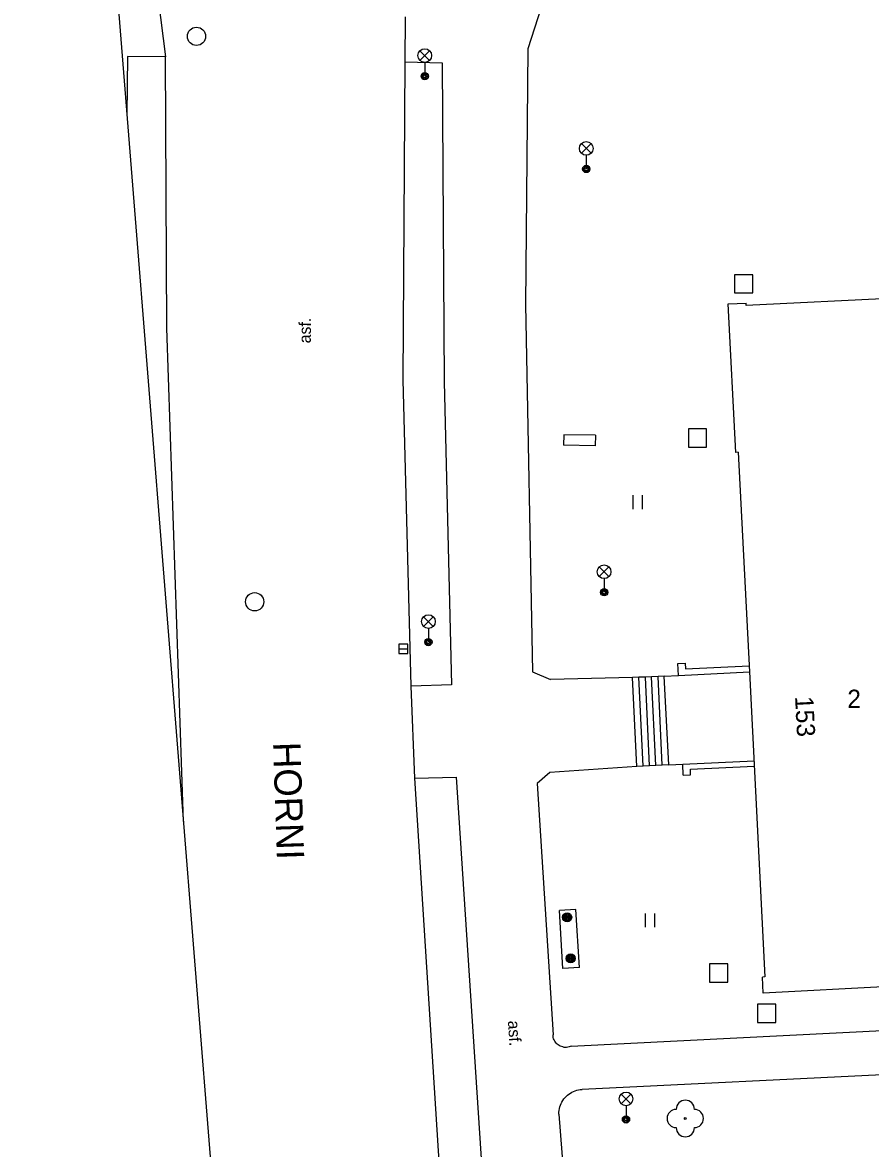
# Model space of a CAD drawing. Extents: x -641829 to -641525, y -1114855 to -1114359.
# Drawn here: x -641828.7 to -641782.2, y -1114487.2 to -1114425.4 of the extents above; entities that cross this region are included whole.
import ezdxf

# ---------------------------------------------------------------- set-up
doc = ezdxf.new("R2010")
doc.units = 0
for name, color, linetype in [('Vrstva 1', 7, 'Continuous'), ('Vrstva 10', 7, 'Continuous'), ('Vrstva 11', 7, 'Continuous'), ('Vrstva 22', 7, 'Continuous'), ('Vrstva 25', 7, 'Continuous'), ('Vrstva 26', 7, 'Continuous'), ('Vrstva 27', 7, 'Continuous'), ('Vrstva 33', 7, 'Continuous'), ('Vrstva 36', 7, 'Continuous'), ('Vrstva 40', 7, 'Continuous'), ('Vrstva 46', 7, 'Continuous'), ('Vrstva 47', 7, 'Continuous'), ('Vrstva 49', 7, 'Continuous'), ('Vrstva 5', 7, 'Continuous')]:
    doc.layers.add(name, color=color, linetype=linetype)

msp = doc.modelspace()

# ---------------------------------------------------------------- linework, layer by layer
at = {"layer": 'Vrstva 1'}
msp.add_line((-641828.67, -1114358.89), (-641812.64, -1114559.36), dxfattribs=at)
at = {"layer": 'Vrstva 10'}
for p, q in [((-641821.23, -1114424.14), (-641820.82, -1114427.32)), ((-641807.68, -1114427.59), (-641807.67, -1114425.11)), ((-641820.76, -1114442.18), (-641820.82, -1114427.32)), ((-641807.8, -1114445.03), (-641807.68, -1114427.59)), ((-641819.847, -1114469.232), (-641820.76, -1114442.18)), ((-641807.36, -1114461.82), (-641807.8, -1114445.03)), ((-641807.15, -1114466.87), (-641807.36, -1114461.82)), ((-641805.78, -1114488.44), (-641807.15, -1114466.87))]:
    msp.add_line(p, q, dxfattribs=at)
at = {"layer": 'Vrstva 11'}
for p, q in [((-641800.22, -1114424.61), (-641800.95, -1114426.88)), ((-641800.95, -1114426.88), (-641801.09, -1114440.89)), ((-641822.92, -1114427.3), (-641822.945, -1114430.492)), ((-641820.82, -1114427.32), (-641822.92, -1114427.3)), ((-641807.68, -1114427.59), (-641805.66, -1114427.64)), ((-641805.66, -1114427.64), (-641805.54, -1114445.13)), ((-641801.09, -1114440.89), (-641800.69, -1114461.04)), ((-641805.54, -1114445.13), (-641805.15, -1114461.75)), ((-641798.98, -1114448.03), (-641798.99, -1114448.61)), ((-641797.25, -1114448.06), (-641798.98, -1114448.03)), ((-641797.25, -1114448.06), (-641797.26, -1114448.64)), ((-641797.26, -1114448.64), (-641798.99, -1114448.61)), ((-641792.72, -1114460.58), (-641792.32, -1114460.56)), ((-641792.69, -1114461.23), (-641792.72, -1114460.58)), ((-641792.32, -1114460.56), (-641792.3, -1114460.86)), ((-641800.69, -1114461.04), (-641799.72, -1114461.46)), ((-641792.69, -1114461.23), (-641788.8, -1114461.04)), ((-641792.3, -1114460.86), (-641788.82, -1114460.7)), ((-641805.15, -1114461.75), (-641807.36, -1114461.82)), ((-641795.21, -1114461.35), (-641799.72, -1114461.46)), ((-641794.86, -1114461.33), (-641795.21, -1114461.35)), ((-641794.98, -1114466.22), (-641795.21, -1114461.35)), ((-641794.51, -1114461.32), (-641794.86, -1114461.33)), ((-641794.63, -1114466.2), (-641794.86, -1114461.33)), ((-641794.17, -1114461.3), (-641794.51, -1114461.32)), ((-641794.28, -1114466.18), (-641794.51, -1114461.32)), ((-641793.81, -1114461.28), (-641794.17, -1114461.3)), ((-641793.93, -1114466.16), (-641794.17, -1114461.3)), ((-641793.47, -1114461.27), (-641793.81, -1114461.28)), ((-641793.58, -1114466.15), (-641793.81, -1114461.28)), ((-641793.47, -1114461.27), (-641792.69, -1114461.23)), ((-641793.23, -1114466.13), (-641793.47, -1114461.27)), ((-641793.23, -1114466.13), (-641793.58, -1114466.15)), ((-641793.23, -1114466.13), (-641792.45, -1114466.09)), ((-641792.45, -1114466.09), (-641788.55, -1114465.91)), ((-641792.43, -1114466.69), (-641792.45, -1114466.09)), ((-641799.74, -1114466.55), (-641800.44, -1114467.16)), ((-641794.98, -1114466.22), (-641799.74, -1114466.55)), ((-641794.63, -1114466.2), (-641794.98, -1114466.22)), ((-641794.28, -1114466.18), (-641794.63, -1114466.2)), ((-641793.93, -1114466.16), (-641794.28, -1114466.18)), ((-641793.58, -1114466.15), (-641793.93, -1114466.16)), ((-641792.43, -1114466.69), (-641792.03, -1114466.67)), ((-641792.04, -1114466.37), (-641788.54, -1114466.2)), ((-641792.03, -1114466.67), (-641792.04, -1114466.37)), ((-641807.15, -1114466.87), (-641804.88, -1114466.8)), ((-641804.88, -1114466.8), (-641803.1, -1114493.92)), ((-641800.44, -1114467.16), (-641799.57, -1114480.94)), ((-641798.32, -1114474.07), (-641799.22, -1114474.12)), ((-641799.03, -1114477.29), (-641799.22, -1114474.12)), ((-641798.13, -1114477.24), (-641798.32, -1114474.07)), ((-641798.13, -1114477.24), (-641799.03, -1114477.29)), ((-641798.58, -1114481.55), (-641766.27, -1114479.92)), ((-641799.57, -1114481.01), (-641799.57, -1114480.94)), ((-641799.56, -1114481.08), (-641799.57, -1114481.01)), ((-641799.54, -1114481.15), (-641799.56, -1114481.08)), ((-641799.51, -1114481.21), (-641799.54, -1114481.15)), ((-641799.48, -1114481.28), (-641799.51, -1114481.21)), ((-641799.44, -1114481.34), (-641799.48, -1114481.28)), ((-641799.4, -1114481.39), (-641799.44, -1114481.34)), ((-641799.35, -1114481.44), (-641799.4, -1114481.39)), ((-641799.3, -1114481.49), (-641799.35, -1114481.44)), ((-641799.24, -1114481.52), (-641799.3, -1114481.49)), ((-641799.18, -1114481.56), (-641799.24, -1114481.52)), ((-641799.11, -1114481.58), (-641799.18, -1114481.56)), ((-641799.04, -1114481.6), (-641799.11, -1114481.58)), ((-641798.63, -1114481.57), (-641798.69, -1114481.59)), ((-641798.58, -1114481.55), (-641798.63, -1114481.57)), ((-641798.97, -1114481.62), (-641799.04, -1114481.6)), ((-641798.9, -1114481.62), (-641798.97, -1114481.62)), ((-641798.83, -1114481.62), (-641798.9, -1114481.62)), ((-641798.76, -1114481.61), (-641798.83, -1114481.62)), ((-641798.69, -1114481.59), (-641798.76, -1114481.61)), ((-641758.49, -1114482), (-641797.98, -1114483.93)), ((-641798.54, -1114484.08), (-641798.45, -1114484.04)), ((-641798.45, -1114484.04), (-641798.36, -1114484)), ((-641798.36, -1114484), (-641798.27, -1114483.97)), ((-641798.27, -1114483.97), (-641798.17, -1114483.95)), ((-641798.17, -1114483.95), (-641798.08, -1114483.94)), ((-641798.08, -1114483.94), (-641797.98, -1114483.93)), ((-641799.13, -1114484.7), (-641799.09, -1114484.62)), ((-641799.09, -1114484.62), (-641799.04, -1114484.53)), ((-641799.04, -1114484.53), (-641798.98, -1114484.45)), ((-641798.98, -1114484.45), (-641798.92, -1114484.38)), ((-641798.92, -1114484.38), (-641798.85, -1114484.31)), ((-641798.85, -1114484.31), (-641798.78, -1114484.24)), ((-641798.78, -1114484.24), (-641798.7, -1114484.18)), ((-641798.7, -1114484.18), (-641798.62, -1114484.13)), ((-641798.62, -1114484.13), (-641798.54, -1114484.08)), ((-641799.25, -1114485.17), (-641799.24, -1114485.08)), ((-641799.25, -1114485.29), (-641799.25, -1114485.17)), ((-641799.24, -1114485.08), (-641799.22, -1114484.98)), ((-641799.22, -1114484.98), (-641799.2, -1114484.89)), ((-641799.2, -1114484.89), (-641799.17, -1114484.79)), ((-641799.17, -1114484.79), (-641799.13, -1114484.7)), ((-641799.25, -1114485.29), (-641798.51, -1114495.08))]:
    msp.add_line(p, q, dxfattribs=at)
at = {"layer": 'Vrstva 22'}
msp.add_circle((-641792.32, -1114485.52), 0.05, dxfattribs=at)
for centre, start, end in [((-641792.32, -1114485.02), 0, 180), ((-641792.82, -1114485.52), 90, 270), ((-641791.82, -1114485.52), 270, 90), ((-641792.32, -1114486.02), 180, 0)]:
    msp.add_arc(centre, 0.5, start, end, dxfattribs=at)
at = {"layer": 'Vrstva 25'}
for centre, radius in [((-641798.8, -1114474.49), 0.25), ((-641798.8, -1114474.49), 0.2), ((-641798.8, -1114474.49), 0.15), ((-641798.8, -1114474.49), 0.1), ((-641798.8, -1114474.49), 0.05), ((-641798.61, -1114476.74), 0.25), ((-641798.61, -1114476.74), 0.2), ((-641798.61, -1114476.74), 0.15), ((-641798.61, -1114476.74), 0.1), ((-641798.61, -1114476.74), 0.05)]:
    msp.add_circle(centre, radius, dxfattribs=at)
at = {"layer": 'Vrstva 26'}
for points in [[(-641789.62, -1114440.26), (-641788.62, -1114440.26), (-641788.62, -1114439.26), (-641789.62, -1114439.26)], [(-641792.15, -1114448.71), (-641791.15, -1114448.71), (-641791.15, -1114447.71), (-641792.15, -1114447.71)], [(-641790.99, -1114478.04), (-641789.99, -1114478.04), (-641789.99, -1114477.04), (-641790.99, -1114477.04)], [(-641788.36, -1114480.25), (-641787.36, -1114480.25), (-641787.36, -1114479.25), (-641788.36, -1114479.25)]]:
    msp.add_lwpolyline(points, close=True, dxfattribs=at)
at = {"layer": 'Vrstva 27'}
msp.add_line((-641808.03, -1114459.77), (-641807.53, -1114459.77), dxfattribs=at)
msp.add_lwpolyline([(-641808.03, -1114460.02), (-641807.53, -1114460.02), (-641807.53, -1114459.52), (-641808.03, -1114459.52)], close=True, dxfattribs=at)
for centre in [(-641819.13, -1114426.19), (-641815.94, -1114457.19)]:
    msp.add_circle(centre, 0.5, dxfattribs=at)
at = {"layer": 'Vrstva 33'}
for p, q in [((-641806.874, -1114427.51), (-641806.346, -1114426.98)), ((-641806.874, -1114426.98), (-641806.346, -1114427.51)), ((-641806.61, -1114427.62), (-641806.61, -1114428.37)), ((-641798.014, -1114432.6), (-641797.486, -1114432.07)), ((-641798.014, -1114432.07), (-641797.486, -1114432.6)), ((-641797.75, -1114432.71), (-641797.75, -1114433.46)), ((-641797.034, -1114455.81), (-641796.506, -1114455.28)), ((-641797.034, -1114455.28), (-641796.506, -1114455.81)), ((-641796.77, -1114455.92), (-641796.77, -1114456.67)), ((-641806.676, -1114458.54), (-641806.144, -1114458.01)), ((-641806.676, -1114458.01), (-641806.144, -1114458.54)), ((-641806.41, -1114458.65), (-641806.41, -1114459.4)), ((-641795.836, -1114484.71), (-641795.304, -1114484.18)), ((-641795.836, -1114484.18), (-641795.304, -1114484.71)), ((-641795.57, -1114484.82), (-641795.57, -1114485.57))]:
    msp.add_line(p, q, dxfattribs=at)
for centre, radius in [((-641806.61, -1114427.245), 0.375), ((-641806.61, -1114428.37), 0.2), ((-641806.61, -1114428.37), 0.145), ((-641806.61, -1114428.37), 0.0876), ((-641797.75, -1114432.335), 0.375), ((-641797.75, -1114433.46), 0.2), ((-641797.75, -1114433.46), 0.145), ((-641797.75, -1114433.46), 0.0876), ((-641796.77, -1114455.545), 0.375), ((-641796.77, -1114456.67), 0.2), ((-641796.77, -1114456.67), 0.145), ((-641796.77, -1114456.67), 0.0876), ((-641806.41, -1114458.275), 0.375), ((-641806.41, -1114459.4), 0.2), ((-641806.41, -1114459.4), 0.145), ((-641806.41, -1114459.4), 0.0876), ((-641795.57, -1114484.445), 0.375), ((-641795.57, -1114485.57), 0.2), ((-641795.57, -1114485.57), 0.145), ((-641795.57, -1114485.57), 0.0876)]:
    msp.add_circle(centre, radius, dxfattribs=at)
at = {"layer": 'Vrstva 36'}
for p, q in [((-641795.174, -1114452.104), (-641795.174, -1114451.352)), ((-641794.674, -1114452.104), (-641794.674, -1114451.352)), ((-641794.494, -1114475.034), (-641794.494, -1114474.282)), ((-641793.994, -1114475.034), (-641793.994, -1114474.282))]:
    msp.add_line(p, q, dxfattribs=at)
at = {"layer": 'Vrstva 5'}
for p, q in [((-641757.86, -1114439.44), (-641788.98, -1114440.95)), ((-641789.97, -1114440.85), (-641788.98, -1114440.81)), ((-641788.98, -1114440.95), (-641788.98, -1114440.81)), ((-641789.55, -1114449), (-641789.97, -1114440.85)), ((-641789.41, -1114448.99), (-641789.55, -1114449)), ((-641789.41, -1114448.99), (-641788.8, -1114461.04)), ((-641788.8, -1114461.04), (-641787.95, -1114477.76)), ((-641787.95, -1114477.76), (-641788.09, -1114477.77)), ((-641788.04, -1114478.65), (-641788.09, -1114477.77)), ((-641781.11, -1114478.29), (-641788.04, -1114478.65))]:
    msp.add_line(p, q, dxfattribs=at)

# ---------------------------------------------------------------- texts
at = {"layer": 'Vrstva 40'}
for rotation, p in [(89.60906, (-641812.86, -1114443.02)), (273.75939, (-641802.05, -1114480.17))]:
    msp.add_text('asf.', height=0.65, rotation=rotation, dxfattribs=at).set_placement(p)
at = {"layer": 'Vrstva 46'}
msp.add_text('2', height=1, dxfattribs=at).set_placement((-641783.43, -1114463.01))
at = {"layer": 'Vrstva 47'}
msp.add_text('153', height=1, rotation=272.9036, dxfattribs=at).set_placement((-641786.3, -1114462.39))
at = {"layer": 'Vrstva 49'}
msp.add_text('HORNI', height=1.5, rotation=271.92191, dxfattribs=at).set_placement((-641814.93, -1114464.9))

doc.saveas('drawing.dxf')
